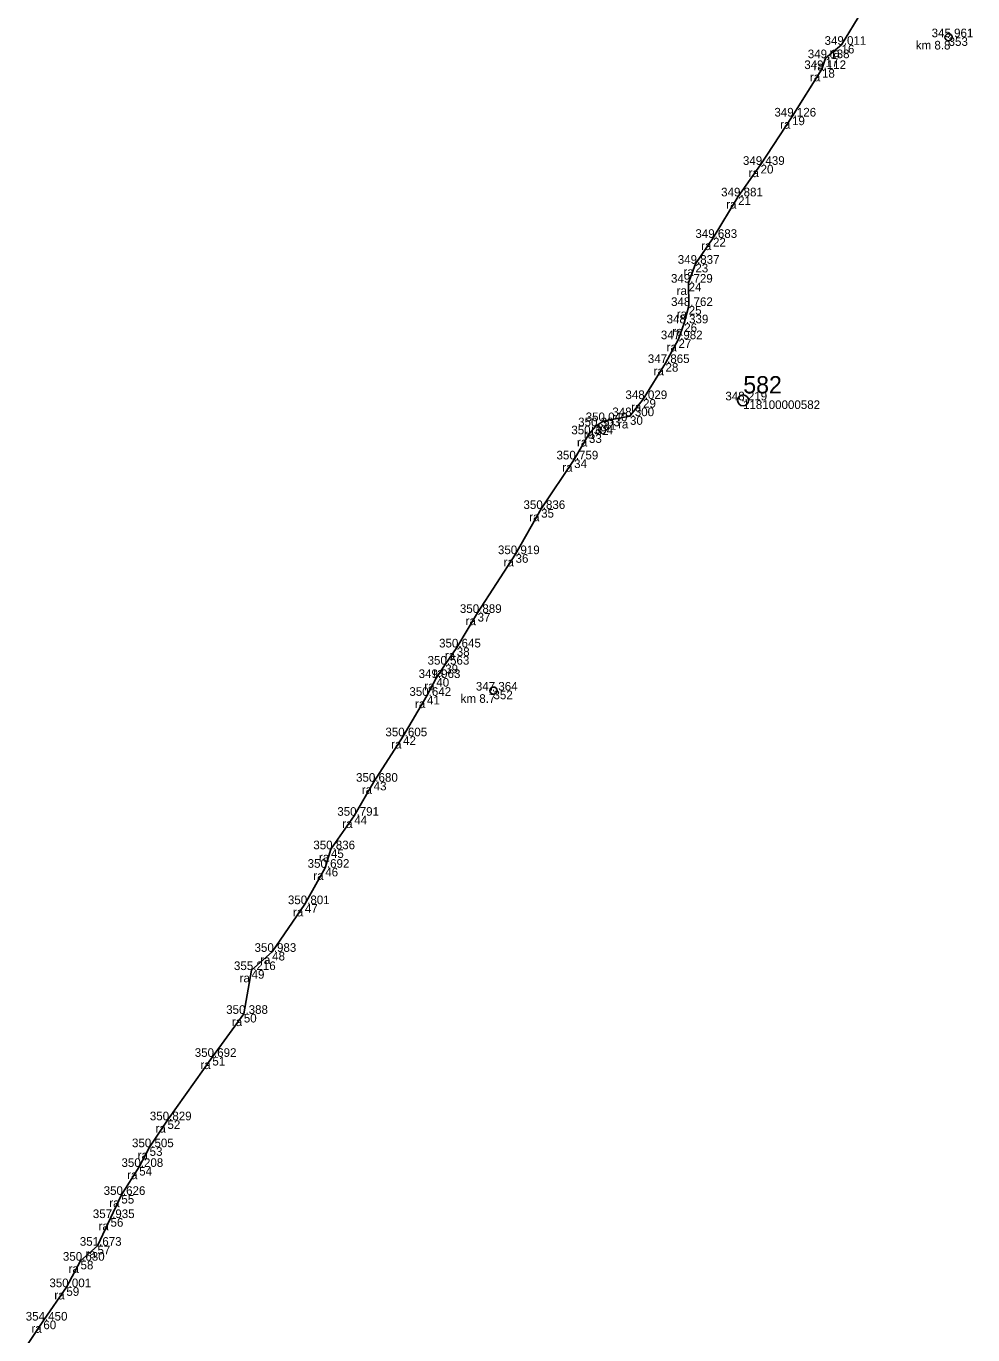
# Model space of a CAD drawing. Extents: x -727171 to -722443, y -945718 to -941834.
# Drawn here: x -725977.3 to -725845.8, y -942944.2 to -942762.3 of the extents above; entities that cross this region are included whole.
import ezdxf

# ---------------------------------------------------------------- set-up
doc = ezdxf.new("R2010")
doc.units = 0
for name, color, linetype in [('Vrstva 28', 7, 'Continuous'), ('Vrstva 60', 7, 'Continuous'), ('Vrstva 61', 7, 'Continuous'), ('Vrstva 62', 7, 'Continuous'), ('Vrstva 63', 7, 'Continuous'), ('Vrstva 7', 7, 'Continuous')]:
    doc.layers.add(name, color=color, linetype=linetype)

msp = doc.modelspace()

# ---------------------------------------------------------------- linework, layer by layer
at = {"layer": 'Vrstva 28'}
msp.add_lwpolyline([(-725861.23, -942760.24), (-725864.03, -942764.88), (-725866.27, -942766.74), (-725866.75, -942768.25), (-725870.91, -942774.85), (-725875.28, -942781.57), (-725878.4, -942785.95), (-725881.89, -942791.72), (-725884.34, -942795.32), (-725885.28, -942797.95), (-725885.27, -942801.19), (-725885.89, -942803.6), (-725886.69, -942805.81), (-725888.49, -942809.12), (-725891.61, -942814.13), (-725893.43, -942816.51), (-725897.14, -942817.2), (-725898.18, -942817.91), (-725899.13, -942819.03), (-725901.19, -942822.52), (-725905.78, -942829.41), (-725909.33, -942835.69), (-725914.61, -942843.86), (-725917.5, -942848.66), (-725919.11, -942851.05), (-725920.35, -942852.91), (-725921.65, -942855.39), (-725924.96, -942861.01), (-725929.05, -942867.33), (-725931.75, -942872.06), (-725934.99, -942876.72), (-725935.78, -942879.29), (-725938.61, -942884.35), (-725943.16, -942890.98), (-725946.02, -942893.51), (-725947.1, -942899.6), (-725951.47, -942905.58), (-725957.71, -942914.4), (-725960.19, -942918.14), (-725961.64, -942920.88), (-725964.12, -942924.77), (-725965.62, -942927.99), (-725967.44, -942931.84), (-725969.79, -942933.92), (-725971.76, -942937.6), (-725974.96, -942942.24), (-725977.26, -942945.7)], dxfattribs=at)
at = {"layer": 'Vrstva 60'}
for p, q in [((-725864.03, -942764.88), (-725864.03, -942764.88)), ((-725849.15, -942763.83), (-725849.15, -942763.83)), ((-725866.27, -942766.74), (-725866.27, -942766.74)), ((-725866.75, -942768.25), (-725866.75, -942768.25)), ((-725870.91, -942774.85), (-725870.91, -942774.85)), ((-725875.28, -942781.57), (-725875.28, -942781.57)), ((-725878.4, -942785.95), (-725878.4, -942785.95)), ((-725881.89, -942791.72), (-725881.89, -942791.72)), ((-725884.34, -942795.32), (-725884.34, -942795.32)), ((-725885.28, -942797.95), (-725885.28, -942797.95)), ((-725885.27, -942801.19), (-725885.27, -942801.19)), ((-725885.89, -942803.6), (-725885.89, -942803.6)), ((-725886.69, -942805.81), (-725886.69, -942805.81)), ((-725888.49, -942809.12), (-725888.49, -942809.12)), ((-725891.61, -942814.13), (-725891.61, -942814.13)), ((-725877.72, -942814.31), (-725877.72, -942814.31)), ((-725893.43, -942816.51), (-725893.43, -942816.51)), ((-725898.18, -942817.91), (-725898.18, -942817.91)), ((-725897.14, -942817.2), (-725897.14, -942817.2)), ((-725899.13, -942819.03), (-725899.13, -942819.03)), ((-725901.19, -942822.52), (-725901.19, -942822.52)), ((-725905.78, -942829.41), (-725905.78, -942829.41)), ((-725909.33, -942835.69), (-725909.33, -942835.69)), ((-725914.61, -942843.86), (-725914.61, -942843.86)), ((-725917.5, -942848.66), (-725917.5, -942848.66)), ((-725919.11, -942851.05), (-725919.11, -942851.05)), ((-725920.35, -942852.91), (-725920.35, -942852.91)), ((-725912.4, -942854.66), (-725912.4, -942854.66)), ((-725921.65, -942855.39), (-725921.65, -942855.39)), ((-725924.96, -942861.01), (-725924.96, -942861.01)), ((-725929.05, -942867.33), (-725929.05, -942867.33)), ((-725931.75, -942872.06), (-725931.75, -942872.06)), ((-725934.99, -942876.72), (-725934.99, -942876.72)), ((-725935.78, -942879.29), (-725935.78, -942879.29)), ((-725938.61, -942884.35), (-725938.61, -942884.35)), ((-725943.16, -942890.98), (-725943.16, -942890.98)), ((-725946.02, -942893.51), (-725946.02, -942893.51)), ((-725947.1, -942899.6), (-725947.1, -942899.6)), ((-725951.47, -942905.58), (-725951.47, -942905.58)), ((-725957.71, -942914.4), (-725957.71, -942914.4)), ((-725960.19, -942918.14), (-725960.19, -942918.14)), ((-725961.64, -942920.88), (-725961.64, -942920.88)), ((-725964.12, -942924.77), (-725964.12, -942924.77)), ((-725965.62, -942927.99), (-725965.62, -942927.99)), ((-725967.44, -942931.84), (-725967.44, -942931.84)), ((-725969.79, -942933.92), (-725969.79, -942933.92)), ((-725971.76, -942937.6), (-725971.76, -942937.6)), ((-725974.96, -942942.24), (-725974.96, -942942.24))]:
    msp.add_line(p, q, dxfattribs=at)
at = {"layer": 'Vrstva 63'}
msp.add_line((-725877.77, -942814.31), (-725877.67, -942814.31), dxfattribs=at)
msp.add_circle((-725877.72, -942814.31), 0.756, dxfattribs=at)
at = {"layer": 'Vrstva 7'}
for p, q in [((-725849.2, -942763.83), (-725849.1, -942763.83)), ((-725912.45, -942854.66), (-725912.35, -942854.66))]:
    msp.add_line(p, q, dxfattribs=at)
for centre in [(-725849.15, -942763.83), (-725912.4, -942854.66)]:
    msp.add_circle(centre, 0.5, dxfattribs=at)

# ---------------------------------------------------------------- texts
at = {"layer": 'Vrstva 60'}
for s, p in [('16', (-725864.03, -942766.08)), ('353', (-725849.15, -942765.03)), ('17', (-725866.27, -942767.94)), ('18', (-725866.75, -942769.45)), ('19', (-725870.91, -942776.05)), ('20', (-725875.28, -942782.77)), ('21', (-725878.4, -942787.15)), ('22', (-725881.89, -942792.92)), ('23', (-725884.34, -942796.52)), ('24', (-725885.28, -942799.15)), ('25', (-725885.27, -942802.39)), ('26', (-725885.89, -942804.8)), ('27', (-725886.69, -942807.01)), ('28', (-725888.49, -942810.32)), ('29', (-725891.61, -942815.33)), ('118100000582', (-725877.72, -942815.51)), ('30', (-725893.43, -942817.71)), ('32', (-725898.18, -942819.11)), ('31', (-725897.14, -942818.4)), ('33', (-725899.13, -942820.22)), ('34', (-725901.19, -942823.72)), ('35', (-725905.78, -942830.61)), ('36', (-725909.33, -942836.89)), ('37', (-725914.61, -942845.06)), ('38', (-725917.5, -942849.86)), ('39', (-725919.11, -942852.24)), ('40', (-725920.35, -942854.11)), ('352', (-725912.4, -942855.86)), ('41', (-725921.65, -942856.59)), ('42', (-725924.96, -942862.21)), ('43', (-725929.05, -942868.53)), ('44', (-725931.75, -942873.26)), ('45', (-725934.99, -942877.92)), ('46', (-725935.78, -942880.49)), ('47', (-725938.61, -942885.55)), ('48', (-725943.16, -942892.18)), ('49', (-725946.02, -942894.71)), ('50', (-725947.1, -942900.8)), ('51', (-725951.47, -942906.78)), ('52', (-725957.71, -942915.6)), ('53', (-725960.19, -942919.34)), ('54', (-725961.64, -942922.08)), ('55', (-725964.12, -942925.97)), ('56', (-725965.62, -942929.19)), ('57', (-725967.44, -942933.04)), ('58', (-725969.79, -942935.12)), ('59', (-725971.76, -942938.8)), ('60', (-725974.96, -942943.44))]:
    msp.add_text(s, height=1.2, dxfattribs=at).set_placement(p)
at = {"layer": 'Vrstva 61'}
for s, p in [('349.011', (-725866.39, -942764.88)), ('345.961', (-725851.51, -942763.83)), ('349.138', (-725868.72, -942766.74)), ('349.112', (-725869.2, -942768.25)), ('349.126', (-725873.36, -942774.85)), ('349.439', (-725877.73, -942781.57)), ('349.881', (-725880.76, -942785.95)), ('349.683', (-725884.34, -942791.72)), ('349.837', (-725886.79, -942795.32)), ('349.729', (-725887.73, -942797.95)), ('348.762', (-725887.72, -942801.19)), ('348.339', (-725888.34, -942803.6)), ('347.982', (-725889.14, -942805.81)), ('347.865', (-725890.95, -942809.12)), ('348.029', (-725894.06, -942814.13)), ('348.219', (-725880.17, -942814.31)), ('350.040', (-725899.59, -942817.2)), ('348.300', (-725895.88, -942816.51)), ('350.394', (-725901.58, -942819.03)), ('350.303', (-725900.63, -942817.91)), ('350.759', (-725903.64, -942822.52)), ('350.836', (-725908.23, -942829.41)), ('350.919', (-725911.78, -942835.69)), ('350.889', (-725917.07, -942843.86)), ('350.645', (-725919.96, -942848.66)), ('350.563', (-725921.56, -942851.05)), ('349.963', (-725922.8, -942852.91)), ('350.642', (-725924.09, -942855.39)), ('347.364', (-725914.85, -942854.66)), ('350.605', (-725927.42, -942861.01)), ('350.680', (-725931.5, -942867.33)), ('350.791', (-725934.11, -942872.06)), ('350.836', (-725937.44, -942876.72)), ('350.692', (-725938.23, -942879.29)), ('350.801', (-725940.97, -942884.35)), ('350.983', (-725945.61, -942890.98)), ('355.216', (-725948.47, -942893.51)), ('350.388', (-725949.55, -942899.6)), ('350.692', (-725953.92, -942905.58)), ('350.829', (-725960.16, -942914.4)), ('350.505', (-725962.64, -942918.14)), ('350.208', (-725964.1, -942920.88)), ('350.626', (-725966.58, -942924.77)), ('357.935', (-725968.08, -942927.99)), ('351.673', (-725969.89, -942931.84)), ('350.630', (-725972.24, -942933.92)), ('350.001', (-725974.12, -942937.6)), ('354.450', (-725977.41, -942942.24))]:
    msp.add_text(s, height=1.2, dxfattribs=at).set_placement(p)
at = {"layer": 'Vrstva 62'}
for s, p in [('km 8.8', (-725853.71, -942765.53)), ('ra', (-725865.7, -942766.58)), ('ra', (-725868.42, -942769.95)), ('ra', (-725867.93, -942768.44)), ('ra', (-725872.57, -942776.55)), ('ra', (-725876.94, -942783.27)), ('ra', (-725880.06, -942787.65)), ('ra', (-725883.55, -942793.42)), ('ra', (-725886, -942797.02)), ('ra', (-725886.94, -942799.65)), ('ra', (-725886.93, -942802.89)), ('ra', (-725887.55, -942805.3)), ('ra', (-725888.35, -942807.51)), ('ra', (-725890.15, -942810.82)), ('ra', (-725893.27, -942815.83)), ('ra', (-725898.8, -942818.9)), ('ra', (-725895.09, -942818.21)), ('ra', (-725900.79, -942820.72)), ('ra', (-725899.84, -942819.61)), ('ra', (-725902.85, -942824.22)), ('ra', (-725907.44, -942831.11)), ('ra', (-725910.99, -942837.39)), ('ra', (-725916.28, -942845.56)), ('ra', (-725919.16, -942850.36)), ('ra', (-725920.77, -942852.74)), ('ra', (-725922.01, -942854.61)), ('ra', (-725923.31, -942857.09)), ('km 8.7', (-725916.96, -942856.36)), ('ra', (-725926.62, -942862.71)), ('ra', (-725930.71, -942869.03)), ('ra', (-725933.42, -942873.76)), ('ra', (-725936.65, -942878.42)), ('ra', (-725937.44, -942880.99)), ('ra', (-725940.27, -942886.05)), ('ra', (-725944.83, -942892.68)), ('ra', (-725947.68, -942895.21)), ('ra', (-725948.76, -942901.3)), ('ra', (-725953.13, -942907.28)), ('ra', (-725959.37, -942916.1)), ('ra', (-725961.85, -942919.84)), ('ra', (-725963.31, -942922.58)), ('ra', (-725965.79, -942926.47)), ('ra', (-725967.29, -942929.69)), ('ra', (-725969.1, -942933.54)), ('ra', (-725971.45, -942935.62)), ('ra', (-725973.43, -942939.3)), ('ra', (-725976.62, -942943.94))]:
    msp.add_text(s, height=1.2, dxfattribs=at).set_placement(p)
at = {"layer": 'Vrstva 63'}
msp.add_text('582', height=2.4, dxfattribs=at).set_placement((-725877.68, -942813.34))

doc.saveas('drawing.dxf')
